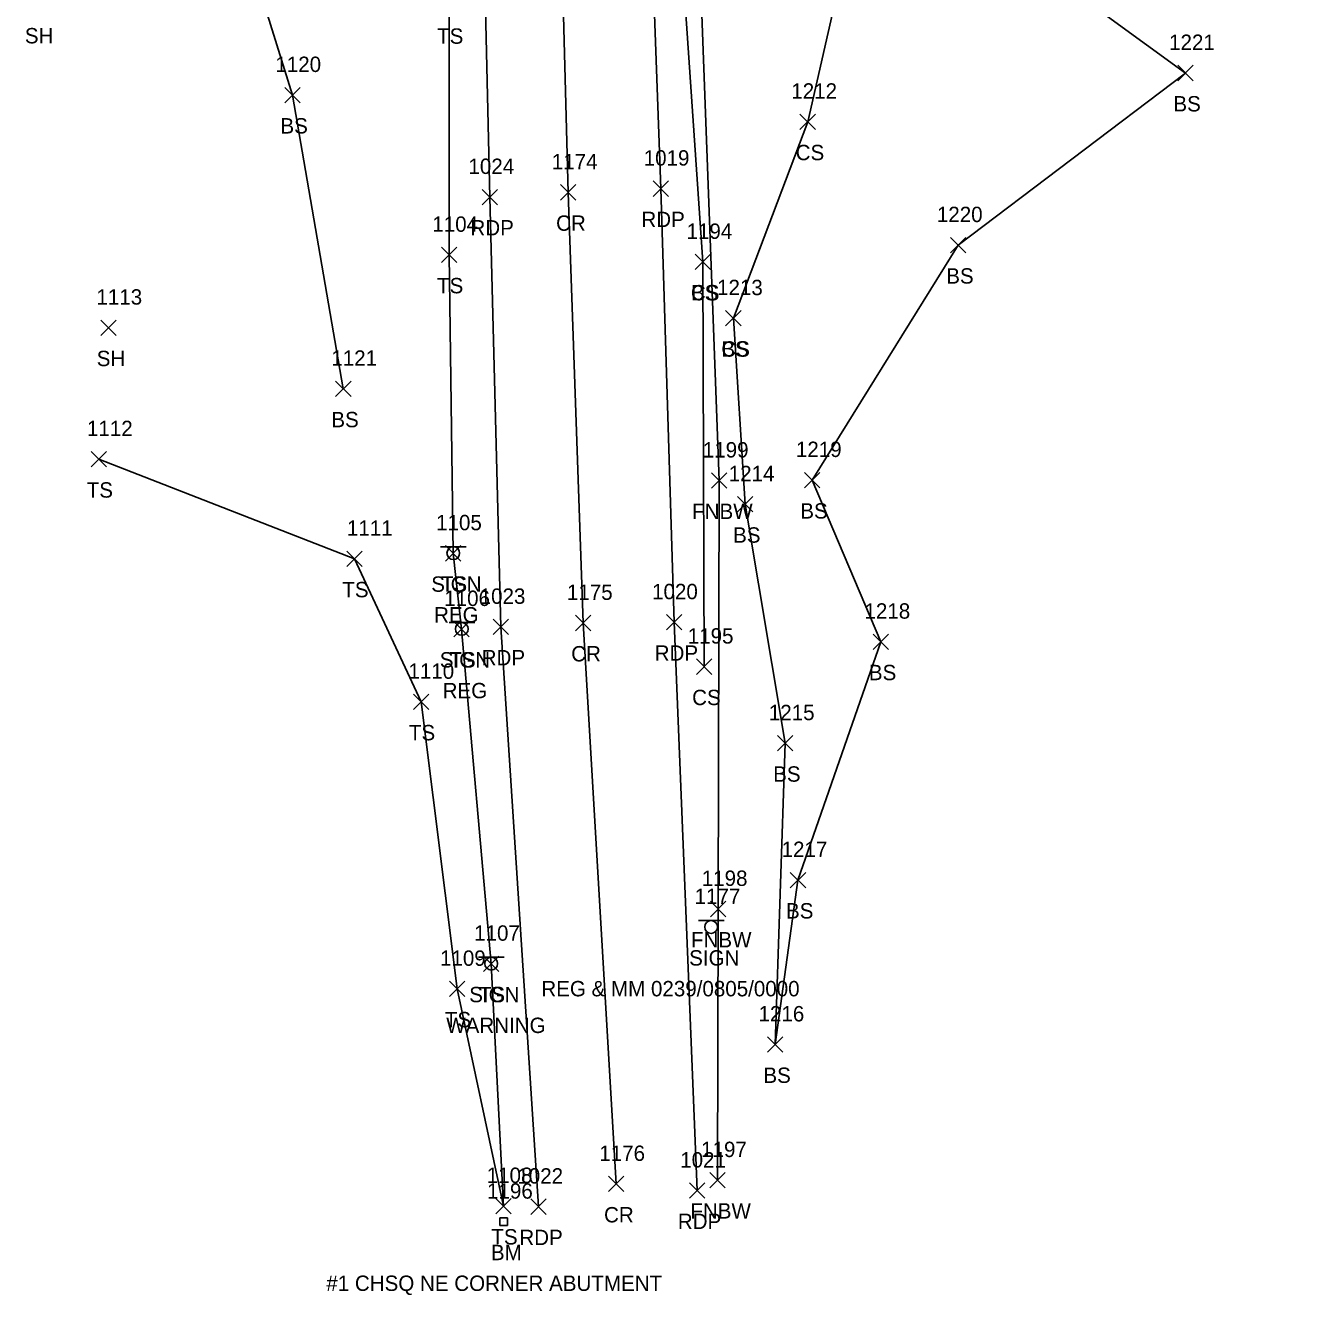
# Model space of a CAD drawing. Extents: x 1609623 to 1616187, y 756677 to 762826.
# Drawn here: x 1610556.9 to 1610724.6, y 761205 to 761370.1 of the extents above; entities that cross this region are included whole.
import ezdxf

# ---------------------------------------------------------------- set-up
doc = ezdxf.new("R2010")
doc.units = 0
for name, color, linetype in [('C_A', 7, 'Continuous'), ('C_C', 7, 'Continuous'), ('C_I', 7, 'Continuous'), ('CPBM', 7, 'Continuous'), ('L_A', 7, 'Continuous'), ('L_I', 7, 'Continuous'), ('L_TIC', 7, 'Continuous'), ('LELB', 7, 'Continuous'), ('LFNC', 7, 'Continuous'), ('P_A', 7, 'Continuous'), ('P_I', 7, 'Continuous'), ('P_TIC', 7, 'Continuous'), ('PET', 7, 'Continuous'), ('PRC', 7, 'Continuous'), ('S_A', 7, 'Continuous'), ('S_C', 7, 'Continuous'), ('S_I', 7, 'Continuous'), ('SSGN', 7, 'Continuous')]:
    doc.layers.add(name, color=color, linetype=linetype)

msp = doc.modelspace()

# ---------------------------------------------------------------- linework, layer by layer
at = {"layer": 'CPBM'}
for p, q in [((1610618.59, 761214.06), (1610618.59, 761215.06)), ((1610618.59, 761215.06), (1610619.59, 761215.06)), ((1610619.59, 761214.06), (1610618.59, 761214.06)), ((1610619.09, 761214.57), (1610619.09, 761214.57)), ((1610619.09, 761214.57), (1610619.09, 761214.57)), ((1610619.59, 761215.06), (1610619.59, 761214.06))]:
    msp.add_line(p, q, dxfattribs=at)
at = {"layer": 'L_TIC'}
for points in [[(1610706.76, 761362.95), (1610708.76, 761364.95)], [(1610708.76, 761362.95), (1610706.76, 761364.95)], [(1610590.59, 761360.08), (1610592.59, 761362.08)], [(1610592.59, 761360.08), (1610590.59, 761362.08)], [(1610657.62, 761356.61), (1610659.62, 761358.61)], [(1610659.62, 761356.61), (1610657.62, 761358.61)], [(1610610.99, 761339.3), (1610612.99, 761341.3)], [(1610612.99, 761339.3), (1610610.99, 761341.3)], [(1610677.21, 761340.56), (1610679.21, 761342.56)], [(1610679.21, 761340.56), (1610677.21, 761342.56)], [(1610643.99, 761338.38), (1610645.99, 761340.38)], [(1610645.99, 761338.38), (1610643.99, 761340.38)], [(1610643.99, 761338.38), (1610645.99, 761340.38)], [(1610645.99, 761338.38), (1610643.99, 761340.38)], [(1610647.95, 761331.06), (1610649.95, 761333.06)], [(1610649.95, 761331.06), (1610647.95, 761333.06)], [(1610647.95, 761331.06), (1610649.95, 761333.06)], [(1610649.95, 761331.06), (1610647.95, 761333.06)], [(1610566.65, 761329.83), (1610568.65, 761331.83)], [(1610568.65, 761329.83), (1610566.65, 761331.83)], [(1610597.21, 761321.88), (1610599.21, 761323.88)], [(1610599.21, 761321.88), (1610597.21, 761323.88)], [(1610565.42, 761312.73), (1610567.42, 761314.73)], [(1610567.42, 761312.73), (1610565.42, 761314.73)], [(1610646.11, 761309.95), (1610648.11, 761311.95)], [(1610648.11, 761309.95), (1610646.11, 761311.95)], [(1610658.22, 761310.01), (1610660.22, 761312.01)], [(1610660.22, 761310.01), (1610658.22, 761312.01)], [(1610649.48, 761306.87), (1610651.48, 761308.87)], [(1610651.48, 761306.87), (1610649.48, 761308.87)], [(1610611.49, 761300.49), (1610613.49, 761302.49)], [(1610613.49, 761300.49), (1610611.49, 761302.49)], [(1610598.67, 761299.77), (1610600.67, 761301.77)], [(1610600.67, 761299.77), (1610598.67, 761301.77)], [(1610612.6, 761290.64), (1610614.6, 761292.64)], [(1610614.6, 761290.64), (1610612.6, 761292.64)], [(1610667.14, 761288.99), (1610669.14, 761290.99)], [(1610669.14, 761288.99), (1610667.14, 761290.99)], [(1610644.15, 761285.75), (1610646.15, 761287.75)], [(1610646.15, 761285.75), (1610644.15, 761287.75)], [(1610607.33, 761281.17), (1610609.33, 761283.17)], [(1610609.33, 761281.17), (1610607.33, 761283.17)], [(1610654.69, 761275.79), (1610656.69, 761277.79)], [(1610656.69, 761275.79), (1610654.69, 761277.79)], [(1610656.36, 761258), (1610658.36, 761260)], [(1610658.36, 761258), (1610656.36, 761260)], [(1610645.97, 761254.24), (1610647.97, 761256.24)], [(1610647.97, 761254.24), (1610645.97, 761256.24)], [(1610616.43, 761247.11), (1610618.43, 761249.11)], [(1610618.43, 761247.11), (1610616.43, 761249.11)], [(1610612.01, 761243.85), (1610614.01, 761245.85)], [(1610614.01, 761243.85), (1610612.01, 761245.85)], [(1610653.41, 761236.62), (1610655.41, 761238.62)], [(1610655.41, 761236.62), (1610653.41, 761238.62)], [(1610645.89, 761218.98), (1610647.89, 761220.98)], [(1610647.89, 761218.98), (1610645.89, 761220.98)], [(1610618.06, 761215.61), (1610620.06, 761217.61)], [(1610620.06, 761215.61), (1610618.06, 761217.61)]]:
    msp.add_lwpolyline(points, dxfattribs=at)
at = {"layer": 'LELB'}
for points in [[(1610665.41, 761590.02), (1610665.86, 761548.38), (1610665.11, 761513.83), (1610666.9, 761479.39), (1610667.05, 761435.65), (1610665.15, 761386.2), (1610658.62, 761357.61), (1610648.95, 761332.06)], [(1610648.95, 761332.06), (1610650.48, 761307.87), (1610655.69, 761276.79), (1610654.41, 761237.62), (1610657.36, 761259), (1610668.14, 761289.99), (1610659.22, 761311.01), (1610678.21, 761341.56), (1610707.76, 761363.95), (1610692.06, 761375.37), (1610682.94, 761389.43), (1610687.92, 761421.37), (1610694.56, 761437.21), (1610693.95, 761448.04), (1610711.57, 761465.17), (1610724.65, 761495.64), (1610720.18, 761535.47), (1610724.49, 761566.5)], [(1610639.38, 761504.91), (1610639.01, 761457.76), (1610640.62, 761403.28), (1610644.99, 761339.38)], [(1610595.41, 761447.25), (1610608.72, 761446.6), (1610609.52, 761429.32), (1610611.27, 761400.91), (1610612, 761372.75), (1610611.99, 761340.3), (1610612.49, 761301.49), (1610613.6, 761291.64), (1610617.43, 761248.11), (1610619.06, 761216.61), (1610613.01, 761244.85), (1610608.33, 761282.17), (1610599.67, 761300.77), (1610566.42, 761313.73)], [(1610582.42, 761390.65), (1610591.59, 761361.08), (1610598.21, 761322.88)], [(1610644.99, 761339.38), (1610645.15, 761286.75)]]:
    msp.add_lwpolyline(points, dxfattribs=at)
at = {"layer": 'LFNC'}
msp.add_lwpolyline([(1610646.89, 761219.98), (1610646.97, 761255.24), (1610647.11, 761310.95), (1610644.58, 761378.59), (1610643.7, 761403.14), (1610643.36, 761458.55), (1610642.07, 761512.84), (1610641.45, 761554.96), (1610639.52, 761588.62)], dxfattribs=at)
at = {"layer": 'P_TIC'}
for points in [[(1610626.46, 761347.43), (1610628.46, 761349.43)], [(1610628.46, 761347.43), (1610626.46, 761349.43)], [(1610638.5, 761347.91), (1610640.5, 761349.91)], [(1610640.5, 761347.91), (1610638.5, 761349.91)], [(1610616.26, 761346.82), (1610618.26, 761348.82)], [(1610618.26, 761346.82), (1610616.26, 761348.82)], [(1610617.72, 761290.92), (1610619.72, 761292.92)], [(1610619.72, 761290.92), (1610617.72, 761292.92)], [(1610628.43, 761291.43), (1610630.43, 761293.43)], [(1610630.43, 761291.43), (1610628.43, 761293.43)], [(1610640.24, 761291.52), (1610642.24, 761293.52)], [(1610642.24, 761291.52), (1610640.24, 761293.52)], [(1610632.7, 761218.48), (1610634.7, 761220.48)], [(1610634.7, 761218.48), (1610632.7, 761220.48)], [(1610643.25, 761217.62), (1610645.25, 761219.62)], [(1610645.25, 761217.62), (1610643.25, 761219.62)], [(1610622.62, 761215.53), (1610624.62, 761217.53)], [(1610624.62, 761215.53), (1610622.62, 761217.53)]]:
    msp.add_lwpolyline(points, dxfattribs=at)
at = {"layer": 'PET'}
for points in [[(1610639.94, 761592.79), (1610633.12, 761589.03), (1610634.88, 761538.15), (1610635.83, 761493.54), (1610636.83, 761445.6), (1610637.66, 761400.17), (1610639.5, 761348.91), (1610641.24, 761292.52), (1610644.25, 761218.62)], [(1610623.62, 761216.53), (1610618.72, 761291.92), (1610617.26, 761347.82), (1610616.06, 761400.59), (1610615, 761443.71), (1610614.38, 761469.34), (1610613.18, 761498.39)]]:
    msp.add_lwpolyline(points, dxfattribs=at)
at = {"layer": 'PRC'}
msp.add_lwpolyline([(1610615.34, 761821.26), (1610616.76, 761769.94), (1610617.49, 761726.01), (1610618.27, 761675.99), (1610618.81, 761645.85), (1610620.71, 761596.25), (1610622.2, 761543.73), (1610623.77, 761494.01), (1610624.8, 761445.35), (1610626.12, 761399.37), (1610627.46, 761348.43), (1610629.43, 761292.43), (1610633.7, 761219.48)], dxfattribs=at)
at = {"layer": 'SSGN'}
for p, q in [((1610610.86, 761302.35), (1610614.2, 761302.35)), ((1610612.51, 761301.51), (1610612.51, 761301.51)), ((1610611.97, 761292.5), (1610615.31, 761292.5)), ((1610613.62, 761291.66), (1610613.62, 761291.66)), ((1610644.41, 761253.74), (1610647.74, 761253.74)), ((1610646.06, 761252.9), (1610646.06, 761252.9)), ((1610615.81, 761248.96), (1610619.14, 761248.96)), ((1610617.45, 761248.13), (1610617.45, 761248.13))]:
    msp.add_line(p, q, dxfattribs=at)
for centre in [(1610612.51, 761301.51), (1610613.62, 761291.66), (1610646.06, 761252.9), (1610617.45, 761248.13)]:
    msp.add_circle(centre, 0.833, dxfattribs=at)

# ---------------------------------------------------------------- texts
at = {"layer": 'C_A'}
msp.add_text('BM', height=2, dxfattribs=at).set_placement((1610617.41, 761209.57))
at = {"layer": 'C_C'}
msp.add_text('#1 CHSQ NE CORNER ABUTMENT', height=2, dxfattribs=at).set_placement((1610596, 761205.57))
at = {"layer": 'C_I'}
msp.add_text('1196', height=2, dxfattribs=at).set_placement((1610616.91, 761217.57))
at = {"layer": 'L_A'}
for s, p in [('SH', (1610556.78, 761367.8)), ('TS', (1610610.41, 761367.75)), ('BS', (1610706.2, 761358.95)), ('BS', (1610590.03, 761356.08)), ('CS', (1610657.06, 761352.61)), ('BS', (1610676.65, 761336.56)), ('TS', (1610610.4, 761335.3)), ('CS', (1610643.43, 761334.38)), ('BS', (1610643.43, 761334.38)), ('SH', (1610566.13, 761325.83)), ('CS', (1610647.39, 761327.06)), ('BS', (1610647.39, 761327.06)), ('BS', (1610596.65, 761317.88)), ('TS', (1610564.83, 761308.73)), ('FNBW', (1610643.59, 761305.95)), ('BS', (1610657.66, 761306.01)), ('BS', (1610648.92, 761302.87)), ('TS', (1610598.08, 761295.77)), ('TS', (1610610.9, 761296.49)), ('TS', (1610612.01, 761286.64)), ('BS', (1610666.58, 761284.99)), ('CS', (1610643.59, 761281.75)), ('TS', (1610606.74, 761277.17)), ('BS', (1610654.13, 761271.79)), ('BS', (1610655.8, 761254)), ('FNBW', (1610643.44, 761250.24)), ('TS', (1610615.84, 761243.11)), ('TS', (1610611.42, 761239.85)), ('BS', (1610652.86, 761232.62)), ('FNBW', (1610643.36, 761214.98)), ('TS', (1610617.47, 761211.61))]:
    msp.add_text(s, height=2, dxfattribs=at).set_placement(p)
at = {"layer": 'L_I'}
for s, p in [('1221', (1610705.64, 761366.95)), ('1120', (1610589.37, 761364.08)), ('1212', (1610656.49, 761360.61)), ('1220', (1610675.43, 761344.56)), ('1104', (1610609.79, 761343.3)), ('1194', (1610642.86, 761342.38)), ('1194', (1610642.86, 761342.38)), ('1213', (1610646.83, 761335.06)), ('1213', (1610646.83, 761335.06)), ('1113', (1610566.09, 761333.83)), ('1121', (1610596.65, 761325.88)), ('1112', (1610564.86, 761316.73)), ('1199', (1610644.98, 761313.95)), ('1219', (1610657.09, 761314.01)), ('1214', (1610648.35, 761310.87)), ('1111', (1610598.68, 761303.77)), ('1105', (1610610.28, 761304.49)), ('1106', (1610611.34, 761294.64)), ('1218', (1610666.01, 761292.99)), ('1195', (1610643.02, 761289.75)), ('1110', (1610606.68, 761285.17)), ('1215', (1610653.57, 761279.79)), ('1217', (1610655.23, 761262)), ('1198', (1610644.84, 761258.24)), ('1107', (1610615.23, 761251.11)), ('1109', (1610610.79, 761247.85)), ('1216', (1610652.23, 761240.62)), ('1197', (1610644.76, 761222.98)), ('1108', (1610616.86, 761219.61))]:
    msp.add_text(s, height=2, dxfattribs=at).set_placement(p)
at = {"layer": 'P_A'}
for s, p in [('RDP', (1610614.75, 761342.82)), ('CR', (1610625.89, 761343.43)), ('RDP', (1610636.99, 761343.91)), ('CR', (1610627.86, 761287.43)), ('RDP', (1610638.72, 761287.52)), ('RDP', (1610616.21, 761286.92)), ('CR', (1610632.13, 761214.48)), ('RDP', (1610641.73, 761213.62)), ('RDP', (1610621.11, 761211.53))]:
    msp.add_text(s, height=2, dxfattribs=at).set_placement(p)
at = {"layer": 'P_I'}
for s, p in [('1024', (1610614.49, 761350.82)), ('1174', (1610625.33, 761351.43)), ('1019', (1610637.29, 761351.91)), ('1175', (1610627.3, 761295.43)), ('1020', (1610638.38, 761295.52)), ('1023', (1610615.95, 761294.92)), ('1176', (1610631.51, 761222.48)), ('1021', (1610642.04, 761221.62)), ('1022', (1610620.85, 761219.53))]:
    msp.add_text(s, height=2, dxfattribs=at).set_placement(p)
at = {"layer": 'S_A'}
for p in [(1610609.65, 761296.49), (1610610.76, 761286.64), (1610643.2, 761247.88), (1610614.59, 761243.11)]:
    msp.add_text('SIGN', height=2, dxfattribs=at).set_placement(p)
at = {"layer": 'S_C'}
for s, p in [('REG', (1610610.02, 761292.49)), ('REG', (1610611.13, 761282.64)), ('REG & MM 0239/0805/0000', (1610623.97, 761243.88)), ('WARNING', (1610611.6, 761239.11))]:
    msp.add_text(s, height=2, dxfattribs=at).set_placement(p)
at = {"layer": 'S_I'}
for s, p in [('1105', (1610610.28, 761304.49)), ('1106', (1610611.34, 761294.64)), ('1177', (1610643.91, 761255.88)), ('1107', (1610615.23, 761251.11))]:
    msp.add_text(s, height=2, dxfattribs=at).set_placement(p)

doc.saveas('drawing.dxf')
